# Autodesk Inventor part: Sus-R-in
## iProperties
Created: 2007-12
Part Number: Sus-R-in
Document SubType Name: Modeling
Designer: UJA2299
Density: 1 g/cm^3
Author: UJA2299
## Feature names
1. 回転1 [Revolution]
2. 押し出し1 [Extrusion]
3. 押し出し2 [Extrusion]
